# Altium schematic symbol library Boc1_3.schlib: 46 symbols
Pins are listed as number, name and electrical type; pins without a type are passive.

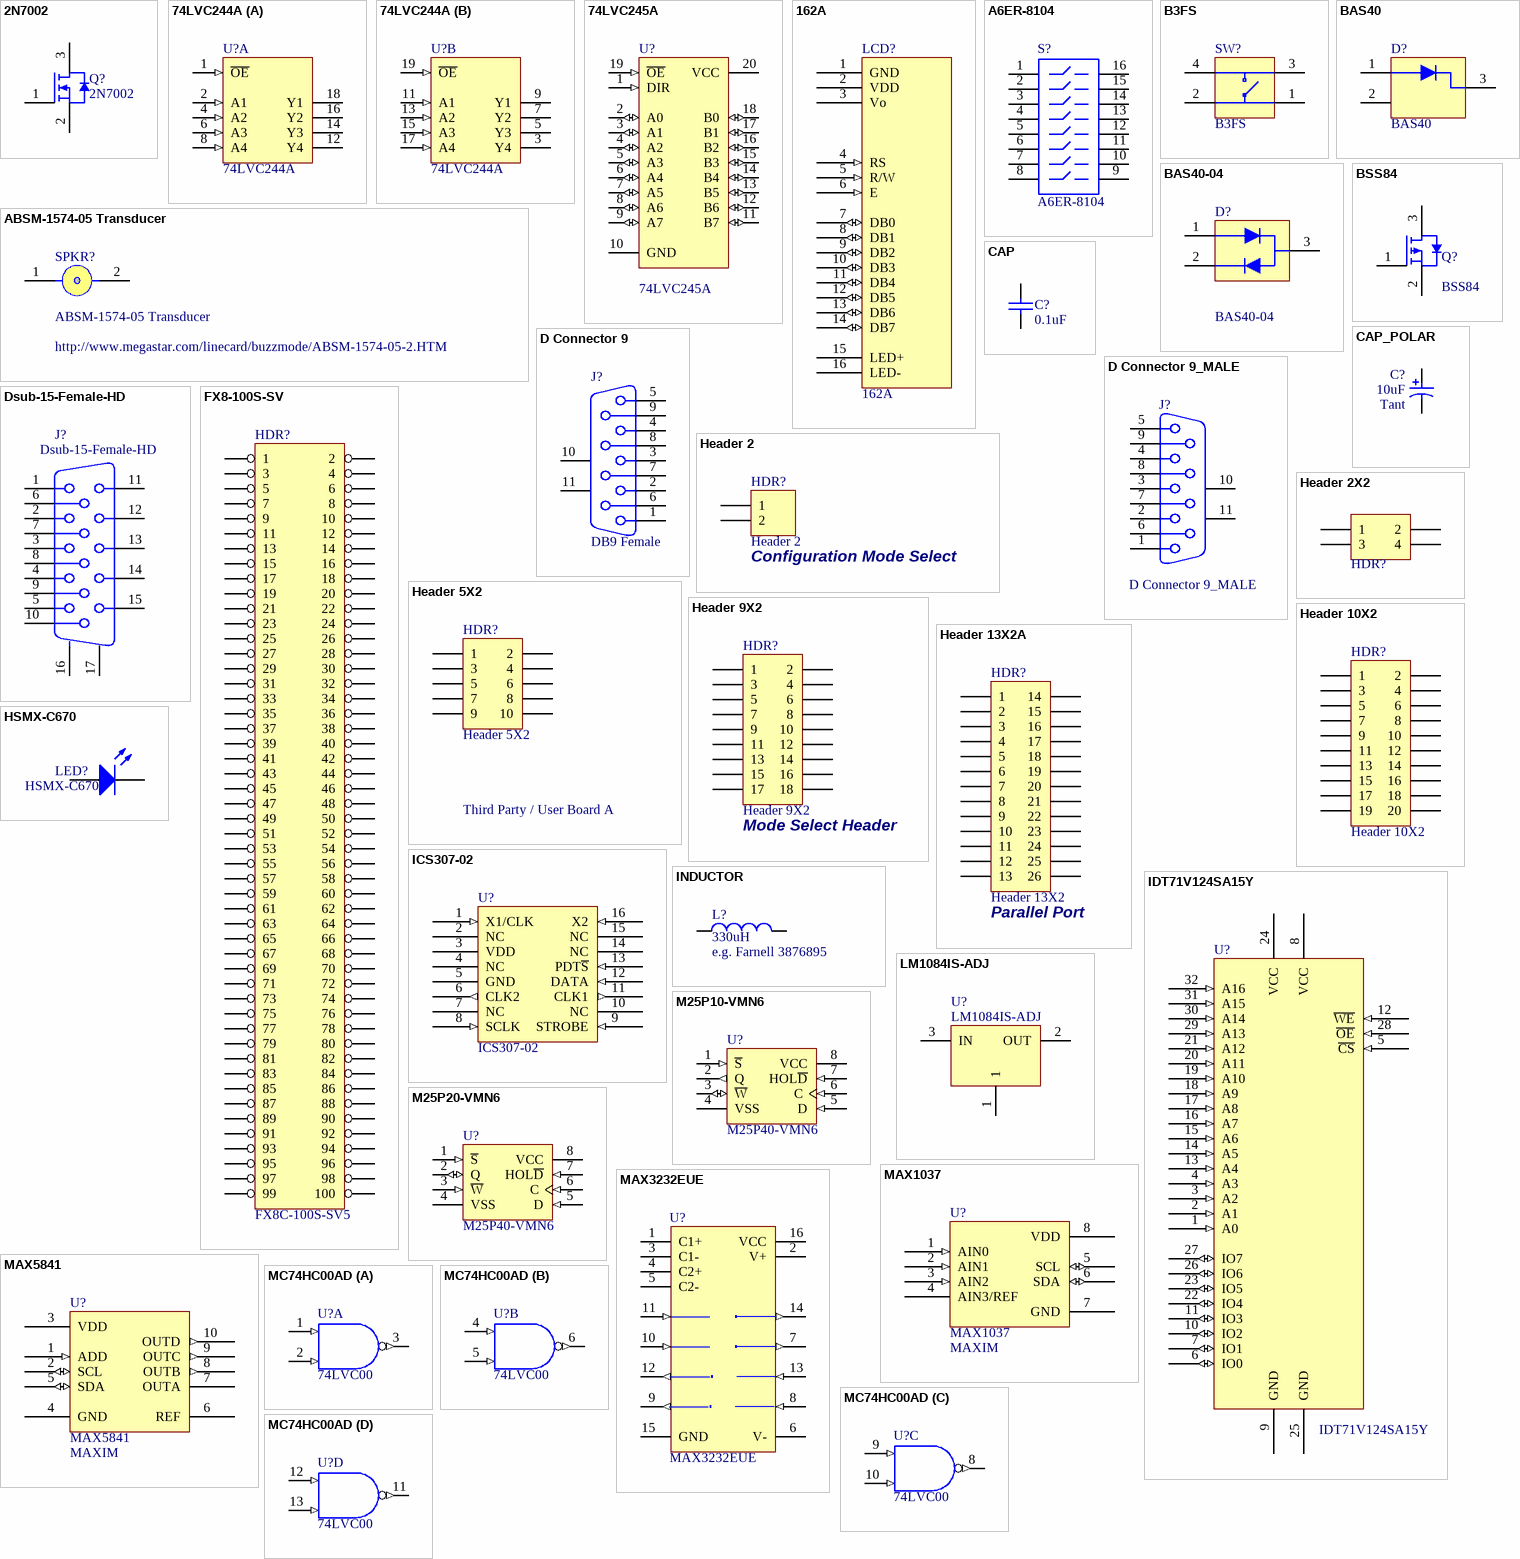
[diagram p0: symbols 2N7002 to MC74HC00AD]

## 2N7002
designator Q?
N Channel Mosfet; Fitted: True
footprint Model Name (Model Description)
footprint SO-G3
pins: 1 "Gate", 2 "Source", 3 "Drain"
1 alternate drawing of the same symbol

## 74LVC244A
designator U?
Octal Buffer/Driver with 3-State Outputs; Manufacturer: Philips; Package Information: Latest Revision: 1998; Class I: Logic; Class II: Buffer/Line Driver; Fitted: True
signal-integrity model SNJ54AHC244FK
footprint SSO-G20/P.65
pins on every part: 10 GND (power) hidden to GND, 20 VCC (power) hidden to VCC
part A pins: 1 ~{OE} (in), 2 A1 (in), 4 A2 (in), 6 A3 (in), 8 A4 (in), 12 Y4 (hiz), 14 Y3 (hiz), 16 Y2 (hiz), 18 Y1 (hiz)
part B pins: 3 Y4 (hiz), 5 Y3 (hiz), 7 Y2 (hiz), 9 Y1 (hiz), 11 A1 (in), 13 A2 (in), 15 A3 (in), 17 A4 (in), 19 ~{OE} (in)

## 74LVC245A
designator U?
Octal Bus Transceiver with 3-State Outputs; Manufacturer: Texas Instruments; Revision 1: 12-July-2000: SIM Model Added.; Revision 2: July-2002: Re-released for DXP Platform.; Class I: Interface; Class II: Line Transceiver; Fitted: True
simulation model SN74F245 (SIMCODE)
signal-integrity model SN54F245J
footprint SSO-G20/P.65
pins: 1 DIR (in), 2 A0 (io), 3 A1 (io), 4 A2 (io), 5 A3 (io), 6 A4 (io), 7 A5 (io), 8 A6 (io), 9 A7 (io), 10 GND (power), 11 B7 (io), 12 B6 (io), 13 B5 (io), 14 B4 (io), 15 B3 (io), 16 B2 (io), 17 B1 (io), 18 B0 (io), 19 ~{OE} (in), 20 VCC (power)

## 162A
designator LCD?
16 char * 2 line LCD character display with b/light; Fitted: True
footprint 162A
pins: 1 GND (power) "VSS - 0V", 2 VDD (power) "VDD - 5V", 3 Vo (hiz) "Input Voltage For LCD", 4 RS (in) "H = Data Signal, L = Instrunction Signal", 5 R/W (in) "H = Read Mode, L = Write Mode", 6 E (in) "Chip Enable (H, H->L)", 7 DB0 (io) "Chip Enable (H, H->L)", 8 DB1 (io) "Chip Enable (H, H->L)", 9 DB2 (io) "Chip Enable (H, H->L)", 10 DB3 (io) "Chip Enable (H, H->L)", 11 DB4 (io) "Chip Enable (H, H->L)", 12 DB5 (io) "Chip Enable (H, H->L)", 13 DB6 (io) "Chip Enable (H, H->L)", 14 DB7 (io) "Chip Enable (H, H->L)", 15 LED+ (power) "LED Backlight +", 16 LED- (power) "LED Backlight -"

## A6ER-8104
designator S?
DIP Switch Side actuator long liver Piano Key; Manufacturer: Generic Components; Fitted: True
footprint DIP-16-KEY
simulation model dpsw8 (Spice Subcircuit)
pins: 1, 2, 3, 4, 5, 6, 7, 8, 9, 10, 11, 12, 13, 14, 15, 16

## ABSM-1574-05 Transducer
designator SPKR?
Megastar Subminiature Transducer; Fitted: True
footprint ABSM-1574 (Magnetic Transducer)
pins: 1, 1A, 2, 2A

## B3FS
designator SW?
SPNA SMD Keyboard Switch; Fitted: True
footprint B3FS_SWITCH
pins: 1, 2, 3, 4

## BAS40
designator D?
Shottky Diode; Fitted: True
footprint SO-G3
pins: 1, 2, 3

## BAS40-04
designator D?
Shottky Diode Pair; Fitted: True
footprint SO-G3
pins: 1, 2, 3

## BSS84
designator Q?
P Channel Mosfet; Fitted: True
footprint Model Name (Model Description)
footprint SO-G3
pins: 1 "Gate", 2 "Source", 3 "Drain"

## CAP
designator C?, comment 0.1uF
Capacitor; Fitted: True
footprint CC1005-0402 (0402 Capacitor)
footprint CC1608-0603 (0603 Capacitor)
footprint CC2012-0805
footprint CC3216-1206 (1206 Capacitor)
footprint CC3225-1210 (1210 Capacitor)
pins: 1, 2

## CAP_POLAR
designator C?, comment 10uF  Capacitor Type: Tant
Polar Capacitor; Fitted: True
footprint MCCT-A (3216 Polar Capacitor)
footprint MCCT-B (3528 Polar Capacitor)
footprint MCCT-C (6032 Polar Capacitor)
footprint MCCT-D (7343 Polar Capacitor)
footprint RB8/3.5
pins: 1, 2

## D Connector 9
designator J?, comment DB9 Female
Receptacle Assembly, 9 Position, Right Angle; Manufacturer: Generic Components; Package Information: Latest Revision: O; Class I: Connector; Positions: 9; Fitted: True
footprint DSUB1.385-2H9
signal-integrity model Connector
pins: 1, 2, 3, 4, 5, 6, 7, 8, 9, 10 MH1, 11 MH2

## D Connector 9_MALE
designator J?
Receptacle Assembly, 9 Position, Right Angle; Manufacturer: Generic Components; Package Information: Latest Revision: O; Positions: 9; Fitted: True
footprint DSUB1.9_MALE
signal-integrity model Connector
pins: 1, 2, 3, 4, 5, 6, 7, 8, 9, 10 MH1, 11 MH2

## Dsub-15-Female-HD
designator J?
Dsub-15 High density VGA Female connetor; Manufacturer: Generic Components; Package Information: Latest Revision: E; Class I: Connector; Positions: 30; Gender: Receptacle Header; Fitted: True
signal-integrity model Connector
footprint DB15-VGA-Female (High density D sub 15 pin Female connector)
pins: 1 "Red Video", 2 "Green Video", 3 "Blue Video", 4 "Monitor ID Bit 2 (Ground)", 5 (power) "Ground", 6 (power) "Red Return (Ground)", 7 (power) "Green Return (Ground)", 8 (power) "Blue Return (Ground)", 9 "Key (not used)", 10 (power) "Sync Return (Ground)", 11 (power) "Monitor ID Bit 0 (Ground)", 12 "Monitor ID Bit 1 (Not Used)", 13 "Horizontal Zync", 14 "Vertical Sync", 15 "Vertical Sync", 16 MH1 "shield", 17 MH2 "shield"

## FX8-100S-SV
designator HDR?, comment FX8C-100S-SV5
Dual row 100 pin SM connector; Fitted: True
footprint FX8-100S-SV
pins: 1, 2, 3, 4, 5, 6, 7, 8, 9, 10, 11, 12, 13, 14, 15, 16, 17, 18, 19, 20, 21, 22, 23, 24, 25, 26, 27, 28, 29, 30, 31, 32, 33, 34, 35, 36, 37, 38, 39, 40, 41, 42, 43, 44, 45, 46, 47, 48, 49, 50, 51, 52, 53, 54, 55, 56, 57, 58, 59, 60, 61, 62, 63, 64, 65, 66, 67, 68, 69, 70, 71, 72, 73, 74, 75, 76, 77, 78, 79, 80, 81, 82, 83, 84, 85, 86, 87, 88, 89, 90, 91, 92, 93, 94, 95, 96, 97, 98, 99, 100

## Header 2
designator HDR?  Usage: Configuration Mode Select
Header, 2-Pin; Manufacturer: Generic Components; Class I: Connector; Fitted: False
footprint HDR1X2
signal-integrity model Connector
pins: 1, 2

## Header 2X2
designator HDR?  (value not drawn)
Header, 2-Pin, Dual row; Manufacturer: Generic Components; Class I: Connector; Fitted: True
footprint HDR2X2
signal-integrity model Connector
footprint HDR2X2_B (2x2 HDR un-numbered)
pins: 1, 2, 3, 4

## Header 5X2
designator HDR?  Usage: Third Party / User Board A
Header, 5-Pin, Dual row; Manufacturer: Generic Components; Class I: Connector; Fitted: True
footprint HDR2X5
signal-integrity model Connector
pins: 1, 2, 3, 4, 5, 6, 7, 8, 9, 10

## Header 9X2
designator HDR?  Usage: Mode Select Header
Header, 9-Pin, Dual row; Manufacturer: Generic Components; Class I: Connector; Fitted: True
footprint HDR2X9
signal-integrity model Connector
pins: 1, 2, 3, 4, 5, 6, 7, 8, 9, 10, 11, 12, 13, 14, 15, 16, 17, 18

## Header 10X2
designator HDR?
Header, 10-Pin, Dual row; Manufacturer: Generic Components; Class I: Connector; Fitted: True
footprint HDR2X10
signal-integrity model Connector
pins: 1, 2, 3, 4, 5, 6, 7, 8, 9, 10, 11, 12, 13, 14, 15, 16, 17, 18, 19, 20

## Header 13X2A
designator HDR?, comment Header 13X2  Usage: Parallel Port
Header, 13-Pin, Dual row; Manufacturer: Generic Components; Class I: Connector; Fitted: True
footprint HDR2X13_CEN
signal-integrity model Connector
pins: 1, 2, 3, 4, 5, 6, 7, 8, 9, 10, 11, 12, 13, 14, 15, 16, 17, 18, 19, 20, 21, 22, 23, 24, 25, 26

## HSMX-C670
designator LED?
Typical RED GaAs SMD LED Agilent make; Manufacturer: Generic Components; Class I: Optoelectronic; Fitted: True
footprint SMD _LED
simulation model LED1 (Diode)
pins: 1 A, 2 K

## ICS307-02
designator U?
Serial Programmable PLL Oscillator; Fitted: True
footprint SO-G16
pins: 1 X1/CLK (in) "Reference Word Devider Input", 2 NC "Reference Word Devider Input", 3 VDD (power) "Positive Supply, 3V3 or 5V", 4 NC, 5 GND (power), 6 CLK2 (out) "Fixed Clock Ref", 7 NC "Crystal connection", 8 SCLK (in) "Serial Programming Clock", 9 STROBE (in) "Serial Programming Strobe", 10 NC, 11 CLK1 (out) "Variable Clock Output", 12 DATA (in) "Serial Programming Data", 13 PDT~{S} (in) "Low = TriState CLK1 and CLK2 and Power Down", 14 NC, 15 NC, 16 X2 (in) "Crystal Terminal"

## IDT71V124SA15Y
designator U?
128K x 8 bit Fast Static RAM; Fitted: True
footprint SO-J32
pins: 1 A0 (in) "Address 0", 2 A1 (in) "Address 1", 3 A2 (in) "Address 3", 4 A3 (in) "Address 3", 5 ~{CS} (in) "Chip Select", 6 IO0 (io) "Data 0", 7 IO1 (io) "Data 1", 8 VCC (power) "Pos Supply", 9 GND (power), 10 IO2 (io) "Data 2", 11 IO3 (io) "Data 3", 12 ~{WE} (in) "Write Enable", 13 A4 (in) "Address 4", 14 A5 (in) "Address 5", 15 A6 (in) "Address 6", 16 A7 (in) "Address 7", 17 A8 (in) "Address 8", 18 A9 (in) "Address 9", 19 A10 (in) "Address 10", 20 A11 (in) "Address 11", 21 A12 (in) "Address 12", 22 IO4 (io) "Data 4", 23 IO5 (io) "Data 5", 24 VCC (power) "Pos Supply", 25 GND (power), 26 IO6 (io) "Data 6", 27 IO7 (io) "Data 7", 28 ~{OE} (in) "Output Enable", 29 A13 (in) "Address 13", 30 A14 (in) "Address 14", 31 A15 (in) "Address 15", 32 A16 (in) "Address 16"

## INDUCTOR
designator L?, comment 330uH  Part No: e.g. Farnell 3876895
Inductor e.g. Farnell 3876895; Fitted: True
footprint DT3316 (Model Description)
footprint CC4532-1812
pins: 1, 2

## LM1084IS-ADJ
designator U?
5A Low Dropout Possitive Regulators; Fitted: True
footprint TO-263 (D2-PACK SIP-G3/P2.54)
pins: 1 "Output", 2 OUT (power) "Output", 3 IN (power) "Input"

## M25P10-VMN6
designator U?, comment M25P40-VMN6
4 Mbit Flash Serial Prom; Fitted: True
footprint SO-G8
pins: 1 ~{S} (in), 2 Q (out) "Serial Output", 3 ~{W} (io) "Serial Output", 4 VSS (power) "Serial Output", 5 D (in) "Serial Input", 6 C (in) "Serial Input", 7 HOL~{D} (in) "Serial Input", 8 VCC (power) "Serial Input"

## M25P20-VMN6
designator U?, comment M25P40-VMN6
4 Mbit Flash Serial Prom; Fitted: True
footprint SO-G8
pins: 1 ~{S} (in), 2 Q (io) "Serial Output", 3 ~{W} (in) "Serial Output", 4 VSS (power) "Serial Output", 5 D (in) "Serial Input", 6 C (in) "Serial Input", 7 HOL~{D} (in) "Serial Input", 8 VCC (power) "Serial Input"

## MAX1037
designator U?  Supplier: MAXIM
4 Channel 8 Bit ADC, I2C interface, 2.7V to 3.6V Supply; Fitted: True
footprint SOT23_8
pins: 1 AIN0 (in) "Analog Input 0", 2 AIN1 (in) "Analog Input 0", 3 AIN2 (in) "Analog Input 0", 4 AIN3/REF (power) "Analog Input 3/ Reference Input", 5 SCL (io) "I2C Clock Line", 6 SDA (io) "I2C Data Line", 7 GND (power), 8 VDD (power) "Positive Supply"

## MAX3232EUE
designator U?
3.0V TO 5.5V, Low-Power, up to 1Mbps, True RS-232 Transceiver Using Four 0.1µF External Capacitor; Manufacturer: Maxim,ST; Package Information: Latest Revision: 21-0066 C; Class I: Communication
footprint SO-G16
pins: 1 C1+, 2 V+ (power), 3 C1-, 4 C2+, 5 C2-, 6 V- (power), 7 T2OUT (out), 8 R2IN (in), 9 R2OUT (out), 10 T2IN (in), 11 T1IN (in), 12 R1OUT (out), 13 R1IN (in), 14 T1OUT (out), 15 GND (power), 16 VCC (power)

## MAX5841
designator U?  Supplier: MAXIM
4 Channel DAC,I2C,2.7V to 5.5V; Fitted: True
footprint uSOP10
pins: 1 ADD (in) "I2C Address Select", 2 SCL (io) "I2C Clock", 3 VDD (power) "Positive Supply 2.7V to 5.5V", 4 GND (power), 5 SDA (io) "GND", 6 REF "Reference Voltage Input 1V to VDD", 7 OUTA "DAC Output", 8 OUTB (out) "DAC Output", 9 OUTC (out) "DAC Output", 10 OUTD (out) "DAC Output"

## MC74HC00AD
designator U?, comment 74LVC00
Quad 2-Input NAND Gate; Manufacturer: Motorola; Package Information: Latest Revision: 1991; Class I: Logic; Fitted: True
footprint SO-G14/Y2.2
signal-integrity model MC74HC00AD
pins on every part: 7 GND (power) hidden to GND, 14 VDD (power) hidden to VCC
part A pins: 1 A (in), 2 B (in), 3 Y (out)
part B pins: 4 A (in), 5 B (in), 6 Y (out)
part C pins: 8 Y (out), 9 A (in), 10 B (in)
part D pins: 11 Y (out), 12 A (in), 13 B (in)

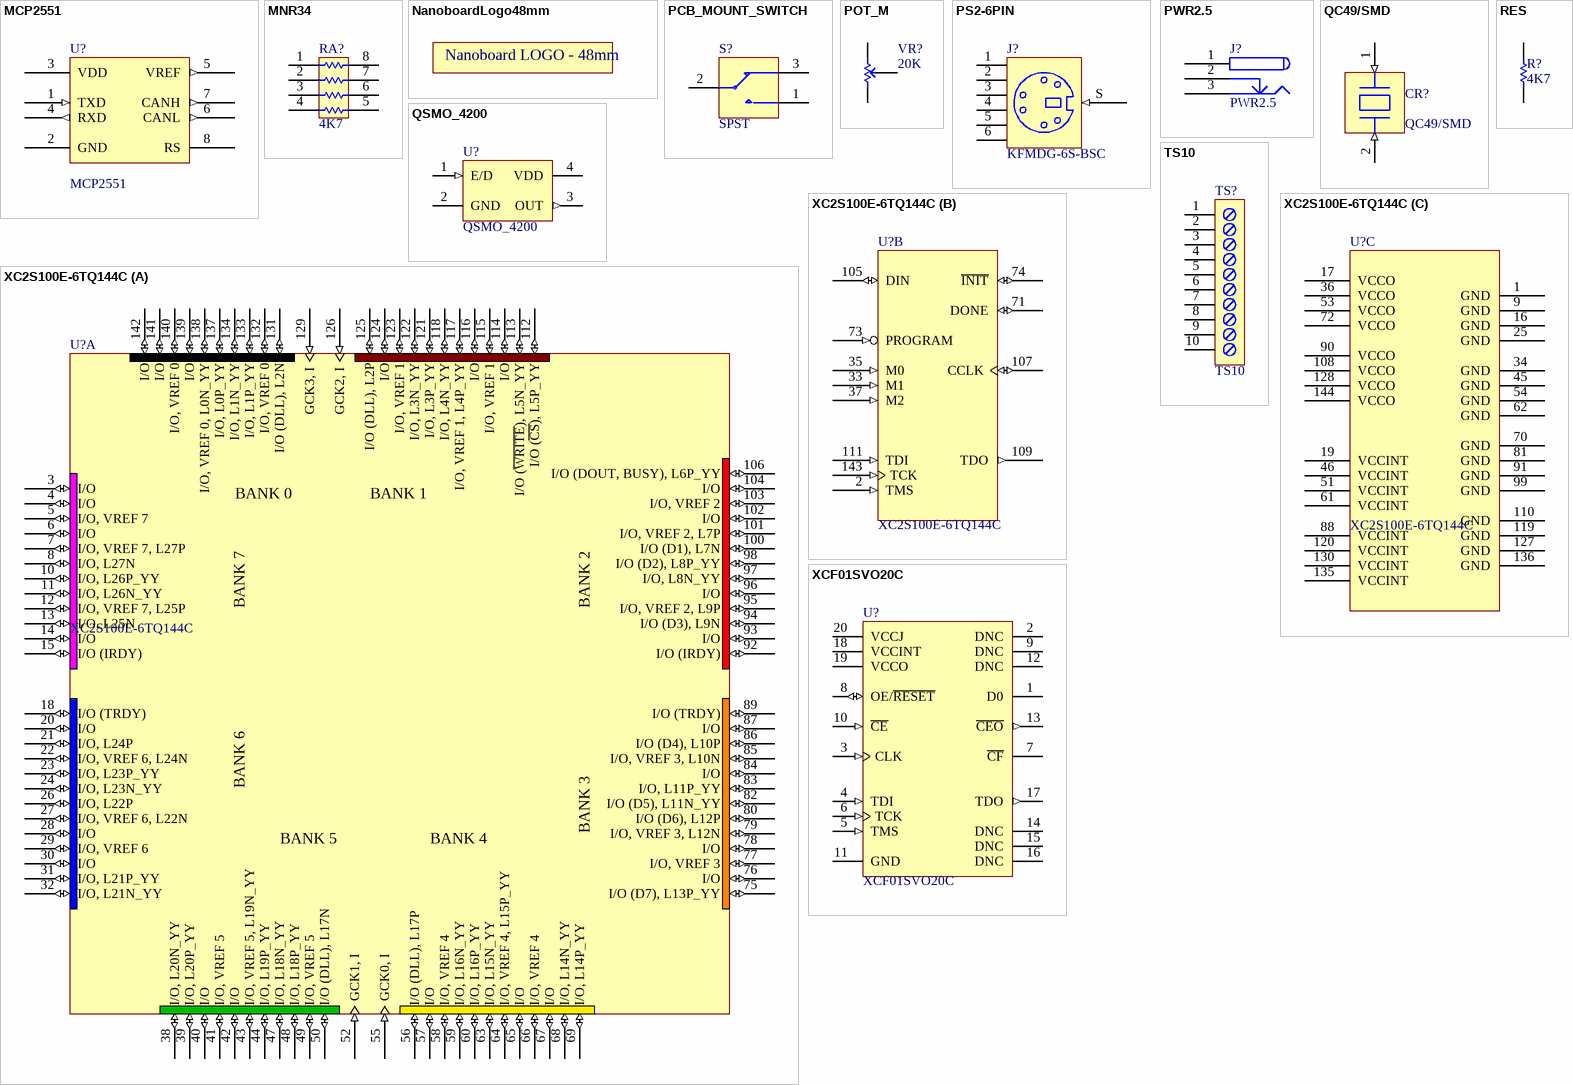
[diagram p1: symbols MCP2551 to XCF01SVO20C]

## MCP2551
designator U?
High Speed Can Transceiver; Fitted: True
footprint SOIC8
pins: 1 TXD (in) "Screw Terminal", 2 GND (power), 3 VDD (power) "Positive Supply 4.5V to 5.5V", 4 RXD (out) "Receive Data", 5 VREF (out) "Reference Voltage", 6 CANL (out) "CAN Bus Low Line", 7 CANH (out) "CAN Bus High Line", 8 RS "Mode/Slope Setting"

## MNR34
designator RA?, comment 4K7
3216x4 Resistor Array; Fitted: True
footprint MNR34 (3216x4 Resistor Array)
pins: 1, 2, 3, 4, 5, 6, 7, 8

## NanoboardLogo48mm
designator LOGO?  (value not drawn)  (graphical)
footprint NanoboardLogo48mm (Satelite board Logo)

## PCB_MOUNT_SWITCH
designator S?, comment SPST
SPDT Subminiature Toggle Switch; Fitted: True
footprint PCB_SWITCH
pins: 1, 2, 3

## POT_M
designator VR?, comment 20K
Potentiometer; Fitted: True
footprint POT4MM (Model Description)
footprint POT4MM-2 (Millison supplied 4mm pot)
pins: CCW -, CW +, W

## PS2-6PIN
designator J?, comment KFMDG-6S-BSC
6 Pin Through Hole PS2 Socket (Kycon P/N); Fitted: True
footprint PS2-6PIN (PS2 Connector)
pins: 1, 2, 3, 4, 5, 6, S (in)

## PWR2.5
designator J?
Low Voltage Power Supply Sonnector; Fitted: True
footprint PWR2.5 (Model Description)
pins: 1 (power), 2 (power), 3 (power)

## QC49/SMD
designator CR?
SMD Crystal 20MHz HY-Q; Fitted: True
footprint QC49/SMD (SMD Crystal)
footprint QC49/SMD (SMD Crystal)
pins: 1 (in), 2 (in)

## QSMO_4200
designator U?
Surface Mount Crystal Oscillator; Fitted: False
footprint QSMO_4200
pins: 1 E/D (in) "Low Disables Clock", 2 GND (power), 3 OUT (out) "Output", 4 VDD (power)

## RES
designator R?, comment 4K7
Resistor; Fitted: True
footprint CC1005-0402 (0402 Resistor)
footprint CC1310-0504 (0504 Resistor)
footprint CC1608-0603 (0603 Resistor)
footprint CC2012-0805 (0805 Resistor)
footprint CC3216-1206 (1206 Resistor)
footprint CC3225-1210 (1210 Resistor)
footprint CC4513-1805 (1805 Resistor)
footprint CC2512 (2512 Resistor)
footprint CC3225-0805
footprint CC1202-0805
pins: 1, 2

## TS10
designator TS?
Screw Terminal Strip, 10 Way, 2.54 mm Pitch; Fitted: True
footprint TS2.54x10 (10 way 2.54mm Pitch screw terminal)
pins: 1 "Screw Terminal", 2 "Screw Terminal", 3 "Screw Terminal", 4 "Screw Terminal", 5 "Screw Terminal", 6 "Screw Terminal", 7 "Screw Terminal", 8 "Screw Terminal", 9 "Screw Terminal", 10 "Screw Terminal"

## XC2S100E-6TQ144C
designator U?
Spartan-IIE 1.8V FPGA, 144-Pin TQFP, Standard Performance, Commercial Grade; Manufacturer: Xilinx; Package Information: Latest Revision: ver1.1, Oct-2002; Class I: Field Programmable Gate Array; Code - JEDEC: MS-026-BFB; Code - IPC: SQFP20X20-144; Fitted: True
footprint TQ144 (144-Pin Thin Quad Flat Pack (TQ144))
3D model XC2S100E-TQ144 (PCB3D Model)
part A pins: 3 I/O (io), 4 I/O (io), 5 I/O, VREF 7 (io), 6 I/O (io), 7 I/O, VREF 7, L27P (io), 8 I/O, L27N (io), 10 I/O, L26P_YY (io), 11 I/O, L26N_YY (io), 12 I/O, VREF 7, L25P (io), 13 I/O, L25N (io), 14 I/O (io), 15 I/O (IRDY) (io), 18 I/O (TRDY) (io), 20 I/O (io), 21 I/O, L24P (io), 22 I/O, VREF 6, L24N (io), 23 I/O, L23P_YY (io), 24 I/O, L23N_YY (io), 26 I/O, L22P (io), 27 I/O, VREF 6, L22N (io), 28 I/O (io), 29 I/O, VREF 6 (io), 30 I/O (io), 31 I/O, L21P_YY (io), 32 I/O, L21N_YY (io), 38 I/O, L20N_YY (io), 39 I/O, L20P_YY (io), 40 I/O (io), 41 I/O, VREF 5 (io), 42 I/O (io), 43 I/O, VREF 5, L19N_YY (io), 44 I/O, L19P_YY (io), 47 I/O, L18N_YY (io), 48 I/O, L18P_YY (io), 49 I/O, VREF 5 (io), 50 I/O (DLL), L17N (io), 52 GCK1, I (in), 55 GCK0, I (in), 56 I/O (DLL), L17P (io), 57 I/O (io), 58 I/O, VREF 4 (io), 59 I/O, L16N_YY (io), 60 I/O, L16P_YY (io), 63 I/O, L15N_YY (io), 64 I/O, VREF 4, L15P_YY (io), 65 I/O (io), 66 I/O, VREF 4 (io), 67 I/O (io), 68 I/O, L14N_YY (io), 69 I/O, L14P_YY (io), 75 I/O (D7), L13P_YY (io), 76 I/O (io), 77 I/O, VREF 3 (io), 78 I/O (io), 79 I/O, VREF 3, L12N (io), 80 I/O (D6), L12P (io), 82 I/O (D5), L11N_YY (io), 83 I/O, L11P_YY (io), 84 I/O (io), 85 I/O, VREF 3, L10N (io), 86 I/O (D4), L10P (io), 87 I/O (io), 89 I/O (TRDY) (io), 92 I/O (IRDY) (io), 93 I/O (io), 94 I/O (D3), L9N (io), 95 I/O, VREF 2, L9P (io), 96 I/O (io), 97 I/O, L8N_YY (io), 98 I/O (D2), L8P_YY (io), 100 I/O (D1), L7N (io), 101 I/O, VREF 2, L7P (io), 102 I/O (io), 103 I/O, VREF 2 (io), 104 I/O (io), 106 I/O (DOUT, BUSY), L6P_YY (io), 112 I/O (~{CS}), L5P_YY (io), 113 I/O (~{WRITE}), L5N_YY (io), 114 I/O (io), 115 I/O, VREF 1 (io), 116 I/O (io), 117 I/O, VREF 1, L4P_YY (io), 118 I/O, L4N_YY (io), 121 I/O, L3P_YY (io), 122 I/O, L3N_YY (io), 123 I/O, VREF 1 (io), 124 I/O (io), 125 I/O (DLL), L2P (io), 126 GCK2, I (in), 129 GCK3, I (in), 131 I/O (DLL), L2N (io), 132 I/O, VREF 0 (io), 133 I/O, L1P_YY (io), 134 I/O, L1N_YY (io), 137 I/O, L0P_YY (io), 138 I/O, VREF 0, L0N_YY (io), 139 I/O (io), 140 I/O, VREF 0 (io), 141 I/O (io), 142 I/O (io)
part B pins: 2 TMS (in), 33 M1 (in), 35 M0 (in), 37 M2 (in), 71 DONE (io), 73 PROGRAM (in), 74 ~{INIT} (io), 105 DIN (io), 107 CCLK (io), 109 TDO (out), 111 TDI (in), 143 TCK (in)
part C pins: 1 GND (power), 9 GND (power), 16 GND (power), 17 VCCO (power), 19 VCCINT (power), 25 GND (power), 34 GND (power), 36 VCCO (power), 45 GND (power), 46 VCCINT (power), 51 VCCINT (power), 53 VCCO (power), 54 GND (power), 61 VCCINT (power), 62 GND (power), 70 GND (power), 72 VCCO (power), 81 GND (power), 88 VCCINT (power), 90 VCCO (power), 91 GND (power), 99 GND (power), 108 VCCO (power), 110 GND (power), 119 GND (power), 120 VCCINT (power), 127 GND (power), 128 VCCO (power), 130 VCCINT (power), 135 VCCINT (power), 136 GND (power), 144 VCCO (power)

## XCF01SVO20C
designator U?
XCF00S Series, Platform Flash In-System Programmable Configuration 3.3V PROM, 1-Megabit, Commercial Grade; Manufacturer: Xilinx; Package Information: Latest Revision: ver1.0, May-2003; Class I: Memory; Code - JEDEC: MO-153-AC; Fitted: True
footprint VO20 (20-Lead TSOP (VO20))
pins: 1 D0 (hiz) "Serial Data Output, for configuring an FPGA in serial mode.", 2 DNC "Leave Unconnected.", 3 CLK (in) "Configuration Clock Input.", 4 TDI (in) "JTAG Serial Data Input.", 5 TMS (in) "JTAG Mode Select Input.", 6 TCK (in) "JTAG Test Clock Input.", 7 ~{CF} (oc) "Configuration Pulse (Open-Drain Output).", 8 OE/~{RESET} (io) "Output Enable/Reset (Open-Drain I/O).", 9 DNC "Leave Unconnected.", 10 ~{CE} (in) "Chip Enable Input.", 11 GND (power) "Ground", 12 DNC "Leave Unconnected.", 13 ~{CEO} (out) "Chip Enable Output, connects to the CE input of the next PROM in the chain.", 14 DNC "Leave Unconnected.", 15 DNC "Leave Unconnected.", 16 DNC "Leave Unconnected.", 17 TDO (out) "JTAG Serial Data Output.", 18 VCCINT (power) "+3.3V Supply for internal logic.", 19 VCCO (power) "+3.3V, 2.5V, or 1.8V I/O Supply.", 20 VCCJ (power) "+3.3V or 2.5V JTAG Signals I/O Supply."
